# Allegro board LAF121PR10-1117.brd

Outline 228.4 x 155.5 mm; copper layers: TOP, GND1, IN1, VCC, IN2, IN3, GND2, BOTTOM. Coordinates in mm from the lower left corner of the outline.

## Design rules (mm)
net group APU-SINGLE CLK: nets 48M_X1 48M_X2
net group APU_DP3_AUX: nets APU_DP3_AUXN APU_DP3_AUXP
net group CSI_CHG: nets CSIN_CHG CSIP_CHG
net group CSO_CHG: nets CSON_CHG CSOP_CHG
net group DIFFPAIR15: nets NCT7718_DXN NCT7718_DXP
net group DIFFPAIR21: nets DDR_A_DQS0 DDR_A_DQS0#
net group DIFFPAIR22: nets DDR_A_DQS1 DDR_A_DQS1#
net group DIFFPAIR23: nets DDR_A_DQS2 DDR_A_DQS2#
net group DIFFPAIR24: nets DDR_A_DQS3 DDR_A_DQS3#
net group DIFFPAIR25: nets DDR_A_CLK0 DDR_A_CLK0#
net group DIFFPAIR26: nets DDR_A_CLK1 DDR_A_CLK1#
net group DIFFPAIR27: nets DDR_A_DQS4 DDR_A_DQS4#
net group DIFFPAIR28: nets DDR_A_DQS5 DDR_A_DQS5#
net group DIFFPAIR29: nets DDR_A_DQS6 DDR_A_DQS6#
net group DIFFPAIR30: nets DDR_A_DQS7 DDR_A_DQS7#
net group DIFFPAIR31: nets DDR_B_DQS0 DDR_B_DQS0#
net group DIFFPAIR32: nets DDR_B_DQS1 DDR_B_DQS1#
net group DIFFPAIR33: nets DDR_B_DQS2 DDR_B_DQS2#
net group DIFFPAIR34: nets DDR_B_DQS3 DDR_B_DQS3#
net group DIFFPAIR35: nets DDR_B_CLK1 DDR_B_CLK1#
net group DIFFPAIR36: nets DDR_B_CLK0 DDR_B_CLK0#
net group DIFFPAIR37: nets DDR_B_DQS4 DDR_B_DQS4#
net group DIFFPAIR38: nets DDR_B_DQS5 DDR_B_DQS5#
net group DIFFPAIR39: nets DDR_B_DQS6 DDR_B_DQS6#
net group DIFFPAIR40: nets DDR_B_DQS7 DDR_B_DQS7#
net group DIFFPAIR42: nets APU_SCLK0 APU_SDATA0
net group DIFFPAIR44: nets EC_SMB_CK2 EC_SMB_DA2
net group DIFFPAIR45: nets A_MIC_CLK A_MIC_DATA
net group DIFFPAIR46: nets EC_SMB_CK1 EC_SMB_DA1
net group DIFFPAIR47: nets TP_CLK TP_DATA
net group DIFFPAIR48: nets HDMI_CTRL_CLK HDMI_CTRL_DATA
net group DIFFPAIR49: nets AUD_HP1_JACK_L1 AUD_HP1_JACK_R1
net group DIFFPAIR54: nets N30684242 N30684245
net group GPU-XTAL_15/18_28/26: nets XTALIN XTALOUT
net group I2C: nets MIC_CLK_C MIC_DATA_C
net group VSUM_APU: nets VSUM+_APU VSUM-_APU
net group VSUM_VGA: nets VSUM+_VGA VSUM-_VGA
net group APU_CLK: nets CLK_PCIE_N1 CLK_PCIE_N2 CLK_PCIE_N3 CLK_PCIE_P1 CLK_PCIE_P2 CLK_PCIE_P3 CLK_PEG_N0 CLK_PEG_P0
net group AUDIO: nets LINE1-L_C LINE1-L_R RING2 RING2_R SLEEVE SLEEVE_R
net group CLK: nets SUSCLK_WLAN
net group CPU: nets H_PROCHOT#
net group DDR-MISCELLANEOUS: nets DDR_A_ALERT# DDR_A_EVENT# DDR_A_RST# DDR_B_ALERT# DDR_B_EVENT# DDR_B_RST#
net group DDR_A_ADD: nets DDR_A_BA0 DDR_A_BA1 DDR_A_BG0 DDR_A_BG1 DDR_A_MA0 DDR_A_MA1 DDR_A_MA2 DDR_A_MA3 DDR_A_MA4 DDR_A_MA5 DDR_A_MA6 DDR_A_MA7 DDR_A_MA8 DDR_A_MA9 DDR_A_MA10 DDR_A_MA11 DDR_A_MA12 DDR_A_MA13
net group DDR_A_CMD: nets DDR_A_ACT# DDR_A_MA14_WE# DDR_A_MA15_CAS# DDR_A_MA16_RAS#
net group DDR_A_CTL: nets DDR_A_CKE0 DDR_A_CKE1 DDR_A_CS0# DDR_A_CS1# DDR_A_ODT0 DDR_A_ODT1 DDR_A_PAR
net group DDR_B_ADD: nets DDR_B_BA0 DDR_B_BA1 DDR_B_BG0 DDR_B_BG1 DDR_B_MA0 DDR_B_MA1 DDR_B_MA2 DDR_B_MA3 DDR_B_MA4 DDR_B_MA5 DDR_B_MA6 DDR_B_MA7 DDR_B_MA8 DDR_B_MA9 DDR_B_MA10 DDR_B_MA11 DDR_B_MA12 DDR_B_MA13
net group DDR_B_CMD: nets DDR_B_ACT# DDR_B_MA14_WE# DDR_B_MA15_CAS# DDR_B_MA16_RAS#
net group DDR_B_CTL: nets DDR_B_CKE0 DDR_B_CKE1 DDR_B_CS0# DDR_B_CS1# DDR_B_ODT0 DDR_B_ODT1 DDR_B_PAR
net group DDRA_D0: nets DDR_A_DM0 DDR_A_DQ0 DDR_A_DQ1 DDR_A_DQ2 DDR_A_DQ3 DDR_A_DQ4 DDR_A_DQ5 DDR_A_DQ6 DDR_A_DQ7
net group DDRA_D1: nets DDR_A_DM1 DDR_A_DQ8 DDR_A_DQ9 DDR_A_DQ10 DDR_A_DQ11 DDR_A_DQ12 DDR_A_DQ13 DDR_A_DQ14 DDR_A_DQ15
net group DDRA_D2: nets DDR_A_DM2 DDR_A_DQ16 DDR_A_DQ17 DDR_A_DQ18 DDR_A_DQ19 DDR_A_DQ20 DDR_A_DQ21 DDR_A_DQ22 DDR_A_DQ23
net group DDRA_D3: nets DDR_A_DM3 DDR_A_DQ24 DDR_A_DQ25 DDR_A_DQ26 DDR_A_DQ27 DDR_A_DQ28 DDR_A_DQ29 DDR_A_DQ30 DDR_A_DQ31
net group DDRA_D4: nets DDR_A_DM4 DDR_A_DQ32 DDR_A_DQ33 DDR_A_DQ34 DDR_A_DQ35 DDR_A_DQ36 DDR_A_DQ37 DDR_A_DQ38 DDR_A_DQ39
net group DDRA_D5: nets DDR_A_DM5 DDR_A_DQ40 DDR_A_DQ41 DDR_A_DQ42 DDR_A_DQ43 DDR_A_DQ44 DDR_A_DQ45 DDR_A_DQ46 DDR_A_DQ47
net group DDRA_D6: nets DDR_A_DM6 DDR_A_DQ48 DDR_A_DQ49 DDR_A_DQ50 DDR_A_DQ51 DDR_A_DQ52 DDR_A_DQ53 DDR_A_DQ54 DDR_A_DQ55
net group DDRA_D7: nets DDR_A_DM7 DDR_A_DQ56 DDR_A_DQ57 DDR_A_DQ58 DDR_A_DQ59 DDR_A_DQ60 DDR_A_DQ61 DDR_A_DQ62 DDR_A_DQ63
net group DDRB_D0: nets DDR_B_DM0 DDR_B_DQ0 DDR_B_DQ1 DDR_B_DQ2 DDR_B_DQ3 DDR_B_DQ4 DDR_B_DQ5 DDR_B_DQ6 DDR_B_DQ7
net group DDRB_D1: nets DDR_B_DM1 DDR_B_DQ8 DDR_B_DQ9 DDR_B_DQ10 DDR_B_DQ11 DDR_B_DQ12 DDR_B_DQ13 DDR_B_DQ14 DDR_B_DQ15
net group DDRB_D2: nets DDR_B_DM2 DDR_B_DQ16 DDR_B_DQ17 DDR_B_DQ18 DDR_B_DQ19 DDR_B_DQ20 DDR_B_DQ21 DDR_B_DQ22 DDR_B_DQ23
net group DDRB_D3: nets DDR_B_DM3 DDR_B_DQ24 DDR_B_DQ25 DDR_B_DQ26 DDR_B_DQ27 DDR_B_DQ28 DDR_B_DQ29 DDR_B_DQ30 DDR_B_DQ31
net group DDRB_D4: nets DDR_B_DM4 DDR_B_DQ32 DDR_B_DQ33 DDR_B_DQ34 DDR_B_DQ35 DDR_B_DQ36 DDR_B_DQ37 DDR_B_DQ38 DDR_B_DQ39
net group DDRB_D5: nets DDR_B_DM5 DDR_B_DQ40 DDR_B_DQ41 DDR_B_DQ42 DDR_B_DQ43 DDR_B_DQ44 DDR_B_DQ45 DDR_B_DQ46 DDR_B_DQ47
net group DDRB_D6: nets DDR_B_DM6 DDR_B_DQ48 DDR_B_DQ49 DDR_B_DQ50 DDR_B_DQ51 DDR_B_DQ52 DDR_B_DQ53 DDR_B_DQ54 DDR_B_DQ55
net group DDRB_D7: nets DDR_B_DM7 DDR_B_DQ56 DDR_B_DQ57 DDR_B_DQ58 DDR_B_DQ59 DDR_B_DQ60 DDR_B_DQ61 DDR_B_DQ62 DDR_B_DQ63
net group DP: nets APU_DP2_AUXN APU_DP2_AUXN_C APU_DP2_AUXP APU_DP2_AUXP_C APU_DP2_N0 APU_DP2_N0_C APU_DP2_N1 APU_DP2_N1_C APU_DP2_P0 APU_DP2_P0_C APU_DP2_P1 APU_DP2_P1_C
net group EDP: nets EDP_AUXN EDP_AUXN_C EDP_AUXP EDP_AUXP_C EDP_TXN0 EDP_TXN0_C EDP_TXN1 EDP_TXN1_C EDP_TXP0 EDP_TXP0_C EDP_TXP1 EDP_TXP1_C
net group HDA: nets HDA_BIT_CLK HDA_BIT_CLK_R HDA_RST# HDA_SDIN0 HDA_SDIN0_R HDA_SDIN1 HDA_SDIN2 HDA_SDOUT HDA_SDOUT_R HDA_SYNC HDA_SYNC_R
net group HDMI: nets APU_DP1_CTRL_CLK APU_DP1_CTRL_DATA APU_DP1_N0 APU_DP1_N1 APU_DP1_N2 APU_DP1_N3 APU_DP1_P0 APU_DP1_P1 APU_DP1_P2 APU_DP1_P3 HDMI_CLKN HDMI_CLKP HDMI_L_CLKN HDMI_L_CLKP HDMI_L_TX_N0 HDMI_L_TX_N1 HDMI_L_TX_N2 HDMI_L_TX_P0 HDMI_L_TX_P1 HDMI_L_TX_P2 HDMI_TX_N0 HDMI_TX_N1 HDMI_TX_N2 HDMI_TX_P0 HDMI_TX_P1 HDMI_TX_P2
net group KB: nets KSI0 KSI1 KSI2 KSI3 KSI4 KSI5 KSI6 KSI7 KSO0 KSO1 KSO2 KSO3 KSO4 KSO5 KSO6 KSO7 KSO8 KSO9 KSO10 KSO11 KSO12 KSO13 KSO14 KSO15
net group LAN: nets LAN_MDIN0 LAN_MDIN1 LAN_MDIN2 LAN_MDIN3 LAN_MDIP0 LAN_MDIP1 LAN_MDIP2 LAN_MDIP3
net group LPC: nets CLKRUN# EC_SCI# LPC_AD0 LPC_AD1 LPC_AD2 LPC_AD3 LPC_CLK0_EC LPC_FRAME# LPC_RST_A# LPCI_CLK_TPM LPCPD# PLT_RST# SERIRQ
net group PCIE: nets PCIE_ARX_C_DTX_N4 PCIE_ARX_C_DTX_P4 PCIE_ARX_DTX_N0 PCIE_ARX_DTX_N1 PCIE_ARX_DTX_N2 PCIE_ARX_DTX_N3 PCIE_ARX_DTX_N4 PCIE_ARX_DTX_N5 PCIE_ARX_DTX_P0 PCIE_ARX_DTX_P1 PCIE_ARX_DTX_P2 PCIE_ARX_DTX_P3 PCIE_ARX_DTX_P4 PCIE_ARX_DTX_P5 PCIE_ATX_C_DRX_N0 PCIE_ATX_C_DRX_N1 PCIE_ATX_C_DRX_N2 PCIE_ATX_C_DRX_N3 PCIE_ATX_C_DRX_N4 PCIE_ATX_C_DRX_N5 PCIE_ATX_C_DRX_P0 PCIE_ATX_C_DRX_P1 PCIE_ATX_C_DRX_P2 PCIE_ATX_C_DRX_P3 PCIE_ATX_C_DRX_P4 PCIE_ATX_C_DRX_P5 PCIE_ATX_DRX_N0 PCIE_ATX_DRX_N1 PCIE_ATX_DRX_N2 PCIE_ATX_DRX_N3 PCIE_ATX_DRX_N4 PCIE_ATX_DRX_N5 PCIE_ATX_DRX_P0 PCIE_ATX_DRX_P1 PCIE_ATX_DRX_P2 PCIE_ATX_DRX_P3 PCIE_ATX_DRX_P4 PCIE_ATX_DRX_P5
net group PEG: nets PEG_ARX_C_GTX_N0 PEG_ARX_C_GTX_N1 PEG_ARX_C_GTX_N2 PEG_ARX_C_GTX_N3 PEG_ARX_C_GTX_P0 PEG_ARX_C_GTX_P1 PEG_ARX_C_GTX_P2 PEG_ARX_C_GTX_P3 PEG_ARX_GTX_N0 PEG_ARX_GTX_N1 PEG_ARX_GTX_N2 PEG_ARX_GTX_N3 PEG_ARX_GTX_P0 PEG_ARX_GTX_P1 PEG_ARX_GTX_P2 PEG_ARX_GTX_P3 PEG_ATX_C_GRX_N0 PEG_ATX_C_GRX_N1 PEG_ATX_C_GRX_N2 PEG_ATX_C_GRX_N3 PEG_ATX_C_GRX_P0 PEG_ATX_C_GRX_P1 PEG_ATX_C_GRX_P2 PEG_ATX_C_GRX_P3 PEG_ATX_GRX_N0 PEG_ATX_GRX_N1 PEG_ATX_GRX_N2 PEG_ATX_GRX_N3 PEG_ATX_GRX_P0 PEG_ATX_GRX_P1 PEG_ATX_GRX_P2 PEG_ATX_GRX_P3
net group RJ45: nets RJ45_MDIN0 RJ45_MDIN1 RJ45_MDIN2 RJ45_MDIN3 RJ45_MDIP0 RJ45_MDIP1 RJ45_MDIP2 RJ45_MDIP3
net group SATA: nets SATA_ARX_C_DTX_N0 SATA_ARX_C_DTX_N1 SATA_ARX_C_DTX_P0 SATA_ARX_C_DTX_P1 SATA_ARX_C_RD_DTX_N0 SATA_ARX_C_RD_DTX_P0 SATA_ARX_DTX_N0 SATA_ARX_DTX_N1 SATA_ARX_DTX_P0 SATA_ARX_DTX_P1 SATA_ARX_RD_DTX_N0 SATA_ARX_RD_DTX_P0 SATA_ATX_C_DRX_N0 SATA_ATX_C_DRX_N1 SATA_ATX_C_DRX_P0 SATA_ATX_C_DRX_P1 SATA_ATX_C_RD_DRX_N0 SATA_ATX_C_RD_DRX_P0 SATA_ATX_DRX_N0 SATA_ATX_DRX_N1 SATA_ATX_DRX_P0 SATA_ATX_DRX_P1 SATA_ATX_RD_DRX_N0 SATA_ATX_RD_DRX_P0 SATA_RX_N0 SATA_RX_P0 SATA_TX_N0 SATA_TX_P0
net group SMBUS: nets CLK_SMB DAT_SMB THM_SML1_CLK THM_SML1_DATA VGA_SMB_CK3 VGA_SMB_DA3
net group SPI: nets APU_SPI_CLK APU_SPI_CLK_R APU_SPI_CS1# APU_SPI_D0 APU_SPI_D1 APU_SPI_D2 APU_SPI_D3 APU_SPI_TPMCS#
net group SPK: nets INT-SPK-L+ INT-SPK-L- INT-SPK-R+ INT-SPK-R- SPK_L+_CONN SPK_L-_CONN SPK_R+_CONN SPK_R-_CONN
net group USB2.0: nets USB20_0_N0 USB20_0_N1 USB20_0_N1_R USB20_0_N2 USB20_0_N2_R USB20_0_N3 USB20_0_N3_R USB20_0_P0 USB20_0_P1 USB20_0_P1_R USB20_0_P2 USB20_0_P2_R USB20_0_P3 USB20_0_P3_R USB20_1_N0 USB20_1_N0_R USB20_1_N1 USB20_1_N1_R USB20_1_P0 USB20_1_P0_R USB20_1_P1 USB20_1_P1_R USB20_CR_N1 USB20_CR_N1_R USB20_CR_P1 USB20_CR_P1_R USB20_FP_N3 USB20_FP_P3 USB20_MINI1_N4 USB20_MINI1_P4 USB20_TOUCH_N2 USB20_TOUCH_P2
net group USB3.0: nets USB3_ARX_C_DTX_0_N1 USB3_ARX_C_DTX_0_N2 USB3_ARX_C_DTX_0_P1 USB3_ARX_C_DTX_0_P2 USB3_ARX_DTX_0_N1 USB3_ARX_DTX_0_N1_R USB3_ARX_DTX_0_N2 USB3_ARX_DTX_0_N2_R USB3_ARX_DTX_0_P1 USB3_ARX_DTX_0_P1_R USB3_ARX_DTX_0_P2 USB3_ARX_DTX_0_P2_R USB3_ATX_C_DRX_0_N1 USB3_ATX_C_DRX_0_N2 USB3_ATX_C_DRX_0_P1 USB3_ATX_C_DRX_0_P2 USB3_ATX_DRX_0_N1 USB3_ATX_DRX_0_N2 USB3_ATX_DRX_0_P1 USB3_ATX_DRX_0_P2 USB3_ATX_L_DRX_0_N1 USB3_ATX_L_DRX_0_N2 USB3_ATX_L_DRX_0_P1 USB3_ATX_L_DRX_0_P2 USB3_DP3_MRX_C_RD_DTX_N0 USB3_DP3_MRX_C_RD_DTX_N3 USB3_DP3_MRX_C_RD_DTX_P0 USB3_DP3_MRX_C_RD_DTX_P3 USB3_DP3_MRX_DTX_N0 USB3_DP3_MRX_DTX_N3 USB3_DP3_MRX_DTX_P0 USB3_DP3_MRX_DTX_P3 USB3_DP3_MRX_L_DTX_N0 USB3_DP3_MRX_L_DTX_N3 USB3_DP3_MRX_L_DTX_P0 USB3_DP3_MRX_L_DTX_P3 USB3_DP3_MRX_RD_DTX_N0 USB3_DP3_MRX_RD_DTX_N3 USB3_DP3_MRX_RD_DTX_P0 USB3_DP3_MRX_RD_DTX_P3 USB3_DP3_MTX_C_DRX_N1 USB3_DP3_MTX_C_DRX_N2 USB3_DP3_MTX_C_DRX_P1 USB3_DP3_MTX_C_DRX_P2 USB3_DP3_MTX_C_RD_DRX_N1 USB3_DP3_MTX_C_RD_DRX_N2 USB3_DP3_MTX_C_RD_DRX_P1 USB3_DP3_MTX_C_RD_DRX_P2 USB3_DP3_MTX_DRX_N1 USB3_DP3_MTX_DRX_N2 USB3_DP3_MTX_DRX_P1 USB3_DP3_MTX_DRX_P2 USB3_DP3_MTX_L_DRX_N1 USB3_DP3_MTX_L_DRX_N2 USB3_DP3_MTX_L_DRX_P1 USB3_DP3_MTX_L_DRX_P2 USB3_DP3_MTX_RD_DRX_N1 USB3_DP3_MTX_RD_DRX_N2 USB3_DP3_MTX_RD_DRX_P1 USB3_DP3_MTX_RD_DRX_P2
net group USB20: nets BOT_MUX_N BOT_MUX_N_R BOT_MUX_P BOT_MUX_P_R TOP_MUX_N TOP_MUX_N_R TOP_MUX_P TOP_MUX_P_R
net group VRAM-ADD0: nets M0_MA0 M0_MA1 M0_MA2 M0_MA3 M0_MA4 M0_MA5 M0_MA6 M0_MA7 M0_MA8
net group VRAM-ADD1: nets M1_MA0 M1_MA1 M1_MA2 M1_MA3 M1_MA4 M1_MA5 M1_MA6 M1_MA7 M1_MA8
net group VRAM-CLK: nets M_CLK0 M_CLK1 M_CLK#0 M_CLK#1
net group VRAM-CTL0: nets M_CAS#0 M_CKE0 M_CS0B#0 M_RAS#0 M_WE#0
net group VRAM-CTL1: nets M_CAS#1 M_CKE1 M_CS1B#0 M_RAS#1 M_WE#1
net group VRAM-D0: nets M_DA0 M_DA1 M_DA2 M_DA3 M_DA4 M_DA5 M_DA6 M_DA7
net group VRAM-D1: nets M_DA8 M_DA9 M_DA10 M_DA11 M_DA12 M_DA13 M_DA14 M_DA15
net group VRAM-D2: nets M_DA16 M_DA17 M_DA18 M_DA19 M_DA20 M_DA21 M_DA22 M_DA23
net group VRAM-D3: nets M_DA24 M_DA25 M_DA26 M_DA27 M_DA28 M_DA29 M_DA30 M_DA31
net group VRAM-D4: nets M_DA32 M_DA33 M_DA34 M_DA35 M_DA36 M_DA37 M_DA38 M_DA39
net group VRAM-D5: nets M_DA40 M_DA41 M_DA42 M_DA43 M_DA44 M_DA45 M_DA46 M_DA47
net group VRAM-D6: nets M_DA48 M_DA49 M_DA50 M_DA51 M_DA52 M_DA53 M_DA54 M_DA55
net group VRAM-D7: nets M_DA56 M_DA57 M_DA58 M_DA59 M_DA60 M_DA61 M_DA62 M_DA63
net group VRAM-DBI: nets M_ADBI0 M_ADBI1 M_DBI0# M_DBI1# M_DBI2# M_DBI3# M_DBI4# M_DBI5# M_DBI6# M_DBI7#
net group VRAM-EDC: nets M_EDC_0 M_EDC_1 M_EDC_2 M_EDC_3 M_EDC_4 M_EDC_5 M_EDC_6 M_EDC_7
net group VRAM-WCK: nets M_WCKA0_0 M_WCKA0_0# M_WCKA0_1 M_WCKA0_1# M_WCKA1_0 M_WCKA1_0# M_WCKA1_1 M_WCKA1_1#
nets with their own width: min track width 0.254; nets +3VLP +3VS_CAM +DP_VDDR +LAN_VDD33 +MPLL_PVDD +SPLL_PVDD +SPLL_VDDC +TSVDD +VDD_CT +VDDR3 KB_LED_PWM
nets with their own width: min track width 0.305; nets +3VS
nets with their own width: min track width 0.381; nets +1.8V_AVDD +3V_DVDD +5V_AVDD +17.4V_BATT+ +FB0_VREFCL +FB0_VREFDL +FB1_VREFCL +FB1_VREFDL +MVREFDA +MVREFSA
nets with their own width: min track width 0.508; nets +1.2VP +1.8VALWP +1.35V_MEM_GFX +2.5VP +3.3V_VDD_PIC +3VALW +5V_CONN_P1 +5VALW +5VS +DP_VDDC +VGA_CORE CCG4_CC1_P1 CCG4_CC2_P1 GND
nets with their own width: min track width 0.864; nets +5V_HDD
nets with their own width: min track width 1.016; nets +0.6V_DDR_VTT +2.5V_MEM MCT1
nets with their own width: min track width 1.219; nets +BIF_VDDC
nets with their own width: min track width 1.524; nets +0.6VSP +5V_HDMI +5VS_ODD +PCIE_VDDC
nets with their own width: min track width 2.032; nets +5V_PVDD +LCDVDD
nets with their own width: min track width 3.048; nets +CCG_VBUS
nets with their own width: min track width 3.81; nets +19VB

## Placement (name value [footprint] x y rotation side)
C1  10P_0402_50V8J  [C_0402]  148.56 56.64 0 top
C5  4.7U_0603_6.3V6K  [C_0603]  215.68 48.26 180 top
C12  0.1U_0603_25V7K  [C_0603]  203.42 59.37 90 top
C13  10U_0603_25V6M  [C_0603]  202.22 59.37 90 top
C14  4.7U_0603_6.3V6K  [C_0603]  214.28 45.78 0 top
C15  0.1U_0402_16V7K  [C_0402]  222.35 48.18 90 top
C16  1U_0402_10V6K  [C_0402]  221.46 48.18 90 top
C18  1U_0402_6.3V6K~D  [C_0402]  117 30.91 90 bottom
C19  10U_0603_10V6M  [C_0603]  95.28 36.25 0 top
C20  100P_0402_50V8J  [C_0402]  127.73 29.15 0 top
C21  100P_0402_50V8J  [C_0402]  127.73 28.27 0 top
C22  .1U_0402_16V7K  [C_0402]  106.21 29.35 270 top
C23  0.01U_0603_25V7K  [C_0603]  36.8 97.21 0 top
C24  1000P_0402_50V7K  [C_0402]  119.74 114.61 180 bottom
C25  0.1U_0402_10V6K  [C_0402]  119.74 115.57 180 bottom
C26  0.1U_0402_10V6K  [C_0402]  126.22 113.53 180 bottom
C27  1000P_0402_50V7K  [C_0402]  119.74 113.66 180 bottom
C28  470P_0402_50V7K  [C_0402]  43.91 98.05 270 top
C29  10U_0805_10V4Z  [C_0805]  49.88 102.64 270 top
C30  10U_0603_10V6M  [C_0603]  51.41 102.48 270 top
C31  0.1U_0402_10V6K  [C_0402]  126.22 112.58 180 bottom
C32  0.1U_0402_10V6K  [C_0402]  124.32 111.82 180 bottom
C33  0.1U_0402_10V6K  [C_0402]  121.62 111.82 0 bottom
C34  1U_0402_6.3V6K  [C_0402]  125.31 114.49 0 bottom
C35  0.01U_0603_25V7K  [C_0603]  33.24 50.67 0 top
C38  470P_0402_50V7K  [C_0402]  40.15 51.05 0 top
C39  10U_0603_6.3V6M  [C_0603]  41.12 55.75 0 top
C40  10U_0603_6.3V6M  [C_0603]  41.12 54.48 0 top
C41  330P_0402_50V7K  [C_0402]  41.07 49.72 180 top
C42  0.1U_0402_16V7K  [C_0402]  35.72 47.29 90 top
C43  1U_0402_6.3V6K  [C_0402]  36.67 47.29 90 top
C44  .1U_0402_16V7K  [C_0402]  37.56 47.29 90 top
C45  4.7U_0603_6.3V6K  [C_0603]  149.58 34.35 270 top
C46  4.7U_0603_6.3V6K  [C_0603]  153.96 39.17 0 top
C47  1U_0402_6.3V6K  [C_0402]  149.07 48.18 90 top
C48  10U_0603_6.3V6M  [C_0603]  31.91 51.37 270 top
C49  10U_0603_6.3V6M  [C_0603]  30.64 51.37 270 top
C50  10U_0603_10V6M  [C_0603]  38.54 100.08 90 top
C51  10U_0603_10V6M  [C_0603]  37.32 100.08 90 top
C52  .1U_0402_16V7K  [C_0402]  145.27 40.51 180 top
C53  10U_0603_6.3V6M  [C_0603]  180.76 62.23 0 top
C54  0.1U_0402_16V7K  [C_0402]  181 63.3 0 top
C55  470P_0603_50V8J  [C_0603]  111.79 110.93 0 bottom
C56  2200P_0402_50V7K  [C_0402]  182.26 61.25 225 bottom
C57  0.1U_0402_16V7K  [C_0402]  177.26 67.24 45 bottom
C58  0.1U_0402_16V7K  [C_0402]  176.63 66.61 225 bottom
C60  10U_0603_10V6M  [C_0603]  212.42 56.07 90 top
C61  0.01U_0402_16V7K  [C_0402]  212.57 53.86 270 top
C65  12P_0402_50V8J~N  [C_0402]  219.41 50.03 0 top
C66  12P_0402_50V8J~N  [C_0402]  216.9 50.03 180 top
C300  0.1U_0402_10V7K  [C_0402]  215.29 38.29 0 top
C301  0.1U_0402_10V7K  [C_0402]  215.29 37.4 0 top
C302  0.1U_0402_10V7K  [C_0402]  215.29 36.51 0 top
C303  0.1U_0402_10V7K  [C_0402]  215.29 35.62 0 top
C304  0.1U_0402_10V7K  [C_0402]  215.29 34.73 0 top
C305  0.1U_0402_10V7K  [C_0402]  215.29 33.84 0 top
C310  1U_0402_10V6K  [C_0402]  212.84 41.4 180 top
C636  10P_0402_50V8J  [C_0402]  120.7 36.32 180 bottom
C796  3.9P_0402_50V8B  [C_0402]  144.43 48.2 270 bottom
C797  3.9P_0402_50V8B  [C_0402]  144.43 49.07 90 bottom
C4311  0.1U_0402_16V7K  [C_0402]  210.8 52 180 bottom
C4312  0.1U_0402_16V7K  [C_0402]  210.8 51.11 180 bottom
C4313  0.1U_0402_16V7K  [C_0402]  210.8 50.22 180 bottom
C4314  0.1U_0402_16V7K  [C_0402]  210.8 49.33 180 bottom
C4321  0.1U_0402_16V7K  [C_0402]  210.8 53.78 180 bottom
C4322  0.1U_0402_16V7K  [C_0402]  210.8 52.89 180 bottom
CA1  10U_0603_10V6M  [C_0603]  31.78 7.68 270 top
CA2  .1U_0402_16V7K  [C_0402]  29.82 7.76 270 top
CA3  10U_0603_10V6M  [C_0603]  33.05 7.68 270 top
CA4  .1U_0402_16V7K  [C_0402]  30.7 7.76 270 top
CA6  10U_0603_10V6M  [C_0603]  21.18 17.27 180 top
CA7  .1U_0402_16V7K  [C_0402]  39.34 20.87 90 top
CA9  10U_0603_10V6M  [C_0603]  32.06 9.29 0 top
CA10  .1U_0402_16V7K  [C_0402]  20.94 18.35 180 top
CA12  10U_0603_10V6M  [C_0603]  21.12 8.25 270 top
CA14  .1U_0402_16V7K  [C_0402]  37.7 20.89 180 top
CA16  10U_0603_10V6M  [C_0603]  36.31 9.08 0 top
CA17  .1U_0402_16V7K  [C_0402]  32.41 15.17 0 top
CA19  10U_0603_10V6M  [C_0603]  19.97 15.24 0 top
CA20  10U_0603_6.3V6M  [C_0603]  23.78 6.15 90 top
CA21  10U_0603_10V6M  [C_0603]  37.56 13.52 180 top
CA23  2.2U_0603_6.3V6K  [C_0603]  21.37 13.97 180 top
CA24  1U_0603_16V7  [C_0603]  22.08 9.7 315 top
CA25  .1U_0402_16V7K  [C_0402]  26.01 22.04 270 top
CA26  .1U_0402_16V7K  [C_0402]  8.92 20.46 270 top
CA27  .1U_0402_16V7K  [C_0402]  22.2 6.97 90 top
CA28  .1U_0402_16V7K  [C_0402]  24.42 21.85 270 top
CA29  .1U_0402_16V7K  [C_0402]  31.1 20.32 180 top
CA30  1000P_0402_50V7K  [C_0402]  22.2 5.19 90 top
CA31  22P_0402_50V8J  [C_0402]  34.32 14.02 90 top
CA37  10U_0603_10V6M  [C_0603]  22.32 18.22 90 top
CA38  10U_0603_10V6M  [C_0603]  23.53 18.22 90 top
CA39  100P_0402_50V8J  [C_0402]  17.29 18.35 0 bottom
CA40  100P_0402_50V8J  [C_0402]  16.43 18.35 180 bottom
CA41  680P_0402_50V8J  [C_0402]  18.21 13.39 180 bottom
CA42  680P_0402_50V8J  [C_0402]  15.45 13.39 0 bottom
CA46  .1U_0402_16V7K  [C_0402]  32.06 10.4 0 top
CA47  0.1U_0402_16V7K  [C_0402]  33.38 16.95 180 top
CA48  .1U_0402_16V7K  [C_0402]  30.64 18.52 90 top
CA49  10P_0402_50V8J  [C_0402]  36.41 12.38 0 top
CA50  10P_0402_50V8J  [C_0402]  36.41 11.49 0 top
CA51  10P_0402_50V8J  [C_0402]  36.41 10.54 0 top
CA52  1000P_0402_50V7K  [C_0402]  27.9 6.28 0 top
CA53  10U_0603_10V6M  [C_0603]  24.99 7.55 270 top
CA54  1U_0603_16V7  [C_0603]  19.91 6.85 90 top
CA55  1000P_0402_50V7K  [C_0402]  26.97 6.28 180 top
CA56  10U_0603_6.3V6M  [C_0603]  26.7 18.73 180 top
CA57  0.1U_0402_16V7K  [C_0402]  27.72 19.41 90 top
CA66  1000P_0402_50V7K  [C_0402]  22.2 3.82 270 top
CA67  680P_0402_50V8J  [C_0402]  15.45 14.35 0 bottom
CA68  680P_0402_50V8J  [C_0402]  18.21 14.35 180 bottom
CC1  .1U_0402_16V7K  [C_0402]  28.69 83.18 180 top
CC2  .1U_0402_16V7K  [C_0402]  28.69 84.07 180 top
CC3  .1U_0402_16V7K  [C_0402]  77.76 116.76 90 bottom
CC4  .1U_0402_16V7K  [C_0402]  76.87 116.76 90 bottom
CC5  27P_0402_50V8F  [C_0402]  145.14 57.34 180 bottom
CC6  27P_0402_50V8F  [C_0402]  148.55 59.24 0 top
CC7  150P_0402_50V8J  [C_0402]  106.78 118.92 90 bottom
CC8  100P_0402_50V8J  [C_0402]  42.67 62.75 0 top
CC9  .1U_0402_16V7K  [C_0402]  43.58 63.7 180 top
CC10  .1U_0402_16V7K  [C_0402]  43.93 61.79 180 top
CC11  0.1U_0402_16V7K  [C_0402]  123.1 57.48 270 top
CC12  0.1U_0402_16V7K  [C_0402]  119.74 50.35 180 top
CC13  0.1U_0402_16V7K  [C_0402]  132.88 46.43 270 top
CC14  0.1U_0402_16V7K  [C_0402]  144.36 57.27 0 top
CC15  1U_0603_25V6K  [C_0603]  119.92 52.19 180 top
CC16  10U_0603_6.3V6M  [C_0603]  119.92 53.46 180 top
CC21  22U_0603_6.3V6M  [C_0603]  94.78 62.92 270 top
CC22  22U_0603_6.3V6M  [C_0603]  92.11 84.32 90 top
CC23  22U_0603_6.3V6M  [C_0603]  116.81 75.05 90 top
CC24  22U_0603_6.3V6M  [C_0603]  61.44 66.73 270 top
CC25  22U_0603_6.3V6M  [C_0603]  83.35 84.39 90 top
CC26  22U_0603_6.3V6M  [C_0603]  96.05 62.92 270 top
CC27  22U_0603_6.3V6M  [C_0603]  90.84 84.32 90 top
CC28  22U_0603_6.3V6M  [C_0603]  93.38 84.32 90 top
CC29  22U_0603_6.3V6M  [C_0603]  97.32 62.92 270 top
CC30  1U_0402_6.3V6K  [C_0402]  101.25 62.62 270 top
CC31  1U_0402_6.3V6K  [C_0402]  100.3 62.62 270 top
CC32  180P_0402_50V8J  [C_0402]  119.29 76.12 90 top
CC33  180P_0402_50V8J  [C_0402]  98.4 62.62 270 top
CC34  180P_0402_50V8J  [C_0402]  99.35 62.62 270 top
CC35  0.22U_0402_10V6K  [C_0402]  117.9 61.08 180 top
CC36  0.22U_0402_10V6K  [C_0402]  116.87 72.18 90 top
CC37  0.22U_0402_10V6K  [C_0402]  94.46 84.56 90 top
CC38  0.22U_0402_10V6K  [C_0402]  95.41 84.56 90 top
CC39  180P_0402_50V8J  [C_0402]  129.07 64.31 90 top
CC40  22U_0603_6.3V6M  [C_0603]  128.76 73.6 90 top
CC41  22U_0603_6.3V6M  [C_0603]  123.99 71.8 270 top
CC42  22U_0603_6.3V6M  [C_0603]  128.71 76.81 90 top
CC43  22U_0603_6.3V6M  [C_0603]  126.42 71.8 270 top
CC44  22U_0603_6.3V6M  [C_0603]  126.32 73.6 90 top
CC45  22U_0603_6.3V6M  [C_0603]  128.86 71.8 270 top
CC46  22U_0603_6.3V6M  [C_0603]  127.54 73.6 90 top
CC47  22U_0603_6.3V6M  [C_0603]  122.77 71.8 270 top
CC48  22U_0603_6.3V6M  [C_0603]  125.1 73.6 90 top
CC49  22U_0603_6.3V6M  [C_0603]  126.27 76.83 90 top
CC50  22U_0603_6.3V6M  [C_0603]  123.88 67.22 90 top
CC51  22U_0603_6.3V6M  [C_0603]  127.49 76.81 90 top
CC52  22U_0603_6.3V6M  [C_0603]  122.67 67.2 90 top
CC53  22U_0603_6.3V6M  [C_0603]  127.64 71.8 270 top
CC54  22U_0603_6.3V6M  [C_0603]  125.21 71.8 270 top
CC55  22U_0603_6.3V6M  [C_0603]  125.09 67.22 90 top
CC56  22U_0603_6.3V6M  [C_0603]  125.05 76.81 90 top
CC57  22U_0603_6.3V6M  [C_0603]  123.83 76.81 90 top
CC58  22U_0603_6.3V6M  [C_0603]  122.61 76.81 90 top
CC59  22U_0603_6.3V6M  [C_0603]  122.67 73.6 90 top
CC60  22U_0603_6.3V6M  [C_0603]  123.88 73.6 90 top
CC61  180P_0402_50V8J  [C_0402]  126.01 79.26 90 top
CC62  1U_0402_6.3V6K  [C_0402]  121.55 79.03 270 top
CC63  22U_0603_6.3V6M  [C_0603]  122.78 79.5 90 top
CC64  22U_0603_6.3V6M  [C_0603]  121.22 73.86 270 top
CC65  10U_0603_6.3V6M  [C_0603]  124.96 62.35 270 top
CC66  22U_0603_6.3V6M  [C_0603]  123.8 43.3 90 top
CC67  1U_0402_6.3V6K  [C_0402]  122.47 43.87 180 bottom
CC68  1U_0402_6.3V6K  [C_0402]  122.47 44.76 180 bottom
CC69  22U_0603_6.3V6M  [C_0603]  117 47.43 90 top
CC70  1U_0402_6.3V6K  [C_0402]  119.03 47.67 90 top
CC71  1U_0402_6.3V6K  [C_0402]  118.08 47.67 90 top
CC72  22U_0603_6.3V6M  [C_0603]  121.76 61.72 90 top
CC73  1U_0402_6.3V6K  [C_0402]  131.78 86.99 0 top
CC74  1U_0402_6.3V6K  [C_0402]  123.08 45.65 0 top
CC75  22U_0603_6.3V6M  [C_0603]  150.78 34.35 270 top
CC76  1U_0402_6.3V6K  [C_0402]  148.5 34.17 270 top
CC77  1U_0402_6.3V6K  [C_0402]  152.82 34.11 270 top
CC78  1U_0402_6.3V6K  [C_0402]  151.86 34.11 270 top
CC79  22U_0603_6.3V6M  [C_0603]  153.96 40.38 0 top
CC80  22U_0603_6.3V6M  [C_0603]  153.96 41.59 0 top
CC81  1U_0402_6.3V6K  [C_0402]  153.44 46.16 0 top
CC82  1U_0402_6.3V6K  [C_0402]  131.5 57.81 270 top
CC83  1U_0402_6.3V6K  [C_0402]  150.91 48.18 90 top
CC84  1U_0402_6.3V6K  [C_0402]  153.44 44.32 0 top
CC85  1U_0402_6.3V6K  [C_0402]  153.44 43.43 0 top
CC86  1U_0402_6.3V6K  [C_0402]  153.44 45.21 0 top
CC87  1U_0402_6.3V6K  [C_0402]  153.44 47.11 0 top
CC88  1U_0402_6.3V6K  [C_0402]  129.02 62.34 90 top
CC89  180P_0402_50V8J  [C_0402]  149.96 48.18 90 top
CC90  0.22U_0402_10V6K  [C_0402]  133.13 34.27 90 bottom
CC91  1U_0402_6.3V6K  [C_0402]  134.08 34.27 90 bottom
CC92  0.1U_0603_25V7K  [C_0603]  151.55 27.94 90 top
CC93  680P_0603_50V8J  [C_0603]  154.85 31.3 180 top
CC94  0.1U_0402_16V7K  [C_0402]  142.97 43.76 270 bottom
CC95  0.1U_0402_16V7K  [C_0402]  142.97 44.62 90 bottom
CC100  150P_0402_50V8J  [C_0402]  111.03 117.55 270 bottom
CC250  0.1U_0402_16V7K  [C_0402]  145.14 58.22 180 bottom
CC251  0.1U_0402_16V7K  [C_0402]  226.3 57.15 180 top
CC615  150P_0402_50V8J  [C_0402]  128.49 43.23 90 top
CC635  .1U_0402_16V7K  [C_0402]  121.62 43.43 0 top
CC682  15P_0402_50V8J  [C_0402]  144.37 53.03 270 bottom
CC686  18P_0402_50V8J  [C_0402]  144.37 53.89 90 bottom
CC1189  1U_0402_6.3V6K  [C_0402]  122.28 51.62 180 top
CC1190  1U_0402_6.3V6K  [C_0402]  122.28 52.57 180 top
CC1191  22U_0603_6.3V6M  [C_0603]  143.54 65.15 0 bottom
CC1192  1U_0402_6.3V6K  [C_0402]  143.85 64.07 0 bottom
CC1193  0.1U_0603_25V7K  [C_0603]  130.53 26.98 270 bottom
CD1  100P_0402_50V8J  [C_0402]  71.54 83.23 90 top
CD2  10U_0603_6.3V6M  [C_0603]  63.41 83.05 90 top
CD3  10U_0603_6.3V6M  [C_0603]  65.95 83.05 90 top
CD4  10U_0603_6.3V6M  [C_0603]  62.65 66.73 270 top
CD5  10U_0603_6.3V6M  [C_0603]  82.08 84.39 90 top
CD6  10U_0603_6.3V6M  [C_0603]  62.14 83.05 90 top
CD7  10U_0603_6.3V6M  [C_0603]  60.87 83.05 90 top
CD8  1U_0402_6.3V6K  [C_0402]  82.58 62.49 270 top
CD9  1U_0402_6.3V6K  [C_0402]  70.65 82.91 90 top
CD10  1U_0402_6.3V6K  [C_0402]  45.68 32 0 top
CD11  1U_0402_6.3V6K  [C_0402]  65.95 66.49 270 top
CD12  1U_0402_6.3V6K  [C_0402]  78.39 84.76 90 top
CD13  1U_0402_6.3V6K  [C_0402]  87.35 62.49 270 top
CD14  1U_0402_6.3V6K  [C_0402]  85.44 62.49 270 top
CD15  1U_0402_6.3V6K  [C_0402]  76.49 84.76 90 top
CD16  1U_0402_6.3V6K  [C_0402]  58.85 43.8 90 top
CD17  10U_0603_6.3V6M  [C_0603]  69.25 42.41 90 top
CD18  10U_0603_6.3V6M  [C_0603]  70.52 42.41 90 top
CD19  10P_0402_50V8J  [C_0402]  83.54 62.49 270 top
CD20  10P_0402_50V8J  [C_0402]  66.9 66.49 270 top
CD21  10P_0402_50V8J  [C_0402]  73.63 84.76 90 top
CD22  10P_0402_50V8J  [C_0402]  57.95 43.8 90 top
CD23  10P_0402_50V8J  [C_0402]  76.04 43.45 90 top
CD24  4.7U_0402_6.3V6K  [C_0402]  71.67 65.53 180 top
CD25  0.1U_0402_16V4Z  [C_0402]  73.05 66.42 0 top
CD26  0.1U_0402_16V4Z  [C_0402]  71.67 66.42 180 top
CD27  2.2U_0402_6.3V6M  [C_0402]  64.99 66.49 270 top
CD28  2.2U_0402_6.3V6M  [C_0402]  84.49 62.49 270 top
CD29  2.2U_0402_6.3V6M  [C_0402]  79.35 84.76 90 top
CD30  2.2U_0402_6.3V6M  [C_0402]  75.09 43.45 90 top
CD31  2.2U_0402_6.3V6M  [C_0402]  74.2 43.45 90 top
CD32  1000P_0402_50V7K  [C_0402]  73.05 65.53 0 top
CD34  10U_0603_6.3V6M  [C_0603]  57.57 49.33 0 top
CD35  330U_D2_2V_Y  [C_D2]  87.73 81 90 top
CD36  1U_0402_6.3V6K  [C_0402]  64.8 42.72 90 top
CD37  10U_0603_6.3V6M  [C_0603]  67.09 42.48 90 top
CD38  1U_0402_6.3V6K  [C_0402]  75.27 45.84 0 top
CD39  1U_0402_6.3V6K  [C_0402]  79.6 43.33 90 top
CD40  100P_0402_50V8J  [C_0402]  59.53 83.93 90 top
CD41  10U_0603_6.3V6M  [C_0603]  63.92 66.73 270 top
CD42  10U_0603_6.3V6M  [C_0603]  84.62 84.39 90 top
CD43  10U_0603_6.3V6M  [C_0603]  64.68 83.05 90 top
CD44  10U_0603_6.3V6M  [C_0603]  78.33 65.53 270 top
CD45  10U_0603_6.3V6M  [C_0603]  67.22 83.05 90 top
CD46  10U_0603_6.3V6M  [C_0603]  69.57 82.99 90 top
CD47  1U_0402_6.3V6K  [C_0402]  77.44 84.76 90 top
CD48  1U_0402_6.3V6K  [C_0402]  74.58 84.76 90 top
CD49  1U_0402_6.3V6K  [C_0402]  86.39 62.49 270 top
CD50  1U_0402_6.3V6K  [C_0402]  96.36 84.56 90 top
CD51  1U_0402_6.3V6K  [C_0402]  80.3 84.76 90 top
CD52  1U_0402_6.3V6K  [C_0402]  68.49 82.91 90 top
CD53  1U_0402_6.3V6K  [C_0402]  81.63 62.49 270 top
CD54  1U_0402_6.3V6K  [C_0402]  75.54 84.76 90 top
CD55  1U_0402_6.3V6K  [C_0402]  68.17 42.65 90 top
CD56  10U_0603_6.3V6M  [C_0603]  71.79 42.41 90 top
CD57  10U_0603_6.3V6M  [C_0603]  73.06 42.41 90 top
CD58  1000P_0402_50V7K  [C_0402]  58.97 66.42 180 top
CD59  4.7U_0402_6.3V6K  [C_0402]  58.64 65.48 270 top
CD60  0.1U_0402_16V4Z  [C_0402]  59.53 65.48 270 top
CD61  0.1U_0402_16V4Z  [C_0402]  58.97 68.07 180 top
CD64  1U_0402_6.3V6K  [C_0402]  78.65 43.33 90 top
CD65  10U_0603_6.3V6M  [C_0603]  57.57 50.54 0 top
CD66  10U_0603_6.3V6M  [C_0603]  65.88 42.48 90 top
CD67  1U_0402_6.3V6K  [C_0402]  65.88 44.88 90 top
CD68  1U_0402_6.3V6K  [C_0402]  77.69 43.33 90 top
CE1  1U_0603_10V6K  [C_0603]  91.03 35.94 90 top
CE2  0.1U_0402_16V7K  [C_0402]  44.93 65.54 270 top
CE3  1000P_0402_50V7K  [C_0402]  54.21 69.85 180 top
CE4  0.1U_0402_16V7K  [C_0402]  40.29 65.54 270 top
CE5  0.1U_0402_16V7K  [C_0402]  31.86 70.35 180 top
CE6  0.1U_0402_16V7K  [C_0402]  37.36 85.28 0 top
CE7  1000P_0402_50V7K  [C_0402]  38.27 86.23 180 top
CE8  0.1U_0402_16V7K  [C_0402]  47.85 86.2 270 top
CE9  0.1U_0402_16V7K  [C_0402]  50.39 85.29 90 top
CE11  100P_0402_50V8J  [C_0402]  53.4 82.76 270 top
CE12  22P_0402_50V8J  [C_0402]  41.18 63.83 270 top
CE13  0.1U_0402_16V7K  [C_0402]  53.3 70.8 0 top
CE14  100P_0402_50V8J  [C_0402]  32.72 77.15 0 top
CE16  1000P_0402_50V7K  [C_0402]  33.64 80.77 180 top
CE17  0.1U_0402_16V7K  [C_0402]  31.86 71.31 180 top
CE18  0.1U_0402_16V7K  [C_0402]  38.52 64.63 90 top
CE19  0.1U_0402_16V7K  [C_0402]  31.53 64.18 90 top
CF1  22U_0805_10V6M  [C_0805]  178.88 69.34 180 top
CH2  0.01U_0402_16V7K  [C_0402]  226.3 58.22 180 top
CH3  0.01U_0402_16V7K  [C_0402]  222.93 67.5 180 top
CH4  0.01U_0402_16V7K  [C_0402]  221.4 64.74 90 top
CI1  0.1U_0402_10V7K  [C_0402]  18.56 94.36 0 top
CI2  0.1U_0402_10V7K  [C_0402]  18.56 93.47 0 top
CI3  .1U_0402_16V7K  [C_0402]  15.9 99.88 0 top
CI4  0.1U_0402_10V7K  [C_0402]  20.91 96.2 0 top
CI5  0.1U_0402_10V7K  [C_0402]  20.91 95.31 0 top
CI6  0.1U_0402_10V7K  [C_0402]  20.91 92.45 0 top
CI7  0.1U_0402_10V7K  [C_0402]  20.91 91.56 0 top
CI8  0.1U_0402_10V7K  [C_0402]  18.56 90.42 0 top
CI9  0.1U_0402_10V7K  [C_0402]  18.56 89.53 0 top
CI10  220P_0402_50V8J  [C_0402]  17.69 106.47 90 top
CL3  1U_0402_6.3V6K  [C_0402]  23.67 88.83 180 top
CL4  .1U_0402_16V7K  [C_0402]  20.3 79.56 180 bottom
CL5  .1U_0402_16V7K  [C_0402]  25.43 82.69 270 bottom
CL6  .1U_0402_16V7K  [C_0402]  23.01 86.48 0 bottom
CL7  0.1U_0402_10V7K  [C_0402]  28.69 85.97 180 top
CL8  0.1U_0402_10V7K  [C_0402]  28.69 86.86 180 top
CL9  0.01U_0402_16V7K  [C_0402]  27.47 69.64 90 top
CL10  10P_1206_2KV8J  [C_1206]  21.5 76.64 0 bottom
CL11  10P_0402_50V8J  [C_0402]  17.75 84.83 90 top
CL12  10P_0402_50V8J  [C_0402]  17.75 83.84 270 top
CL15  .1U_0402_16V7K  [C_0402]  21.62 84.46 270 bottom
CL18  .1U_0402_16V7K  [C_0402]  18.89 81.4 180 top
CL19  .1U_0402_16V7K  [C_0402]  18.73 80.58 180 bottom
CL20  .1U_0402_16V7K  [C_0402]  22.21 79.88 180 bottom
CL21  .1U_0402_16V7K  [C_0402]  24.81 79.94 180 bottom
CL22  1U_0402_10V6K  [C_0402]  22.94 84.74 0 bottom
CL23  .1U_0402_16V7K  [C_0402]  24.74 85.64 270 bottom
CL24  4.7U_0603_6.3V6K  [C_0603]  25.43 83.71 0 bottom
CL25  4.7U_0603_6.3V6K  [C_0603]  21.5 80.83 90 bottom
CLIP2  -  [EMIST_SQ-55G_1P]  84.74 119.23 180 bottom
CLRP1  SHORT PADS  [SHORTPADS]  131.99 34.98 90 bottom
CS1  0.01U_0402_16V7K  [C_0402]  178.75 37 270 top
CS2  0.1U_0402_25V6K  [C_0402]  179.68 37 270 top
CS3  0.01U_0402_16V7K  [C_0402]  179.6 34.98 0 top
CS4  0.01U_0402_16V7K  [C_0402]  179.6 34.09 0 top
CS5  0.01U_0402_16V7K  [C_0402]  179.6 32.32 0 top
CS6  0.01U_0402_16V7K  [C_0402]  179.6 33.21 0 top
CS7  0.01U_0402_16V7K  [C_0402]  188.17 34.16 0 top
CS8  0.01U_0402_16V7K  [C_0402]  188.17 33.27 0 top
CS9  0.01U_0402_16V7K  [C_0402]  188.17 31.43 0 top
CS10  0.01U_0402_16V7K  [C_0402]  188.17 32.32 0 top
CS11  0.01U_0402_16V7K  [C_0402]  191.31 34.16 180 top
CS12  10U_0805_10V6K  [C_0805]  195.3 39.59 90 top
CS13  1000P_0402_50V7K  [C_0402]  193.07 39.99 90 top
CS14  0.1U_0402_25V6K  [C_0402]  193.96 39.99 90 top
CS15  0.01U_0402_16V7K  [C_0402]  191.31 33.27 180 top
CS16  0.01U_0402_16V7K  [C_0402]  191.31 31.43 180 top
CS17  0.01U_0402_16V7K  [C_0402]  191.31 32.32 180 top
CS18  0.01U_0402_16V7K  [C_0402]  188.06 63.74 90 top
CS19  0.01U_0402_16V7K  [C_0402]  188.95 63.74 90 top
CS20  0.1U_0402_25V6K  [C_0402]  203.23 32.9 270 top
CS21  10U_0805_10V6K  [C_0805]  207.4 31.36 0 top
CS22  0.01U_0402_16V7K  [C_0402]  190.72 63.74 90 top
CS23  0.01U_0402_16V7K  [C_0402]  189.84 63.74 90 top
CS24  1000P_0402_50V7K  [C_0402]  196.12 62.87 270 top
CS25  0.1U_0402_25V6K  [C_0402]  195.17 62.87 270 top
CS26  10U_0805_10V6K  [C_0805]  194.12 62.42 180 top
CS29  0.1U_0402_25V6K~D  [C_0402]  28.22 30.54 0 top
CS31  10U_0805_25V6K~D  [C_0805]  22.08 31.59 90 top
CS32  1U_0402_6.3V6K~D  [C_0402]  28.22 29.59 0 top
CS33  1000P_0402_50V7K~D  [C_0402]  28.22 31.43 0 top
CS40  1U_0402_10V6K  [C_0402]  192.82 37.03 270 top
CS44  0.22U_0402_16V7K  [C_0402]  27.34 37.03 270 bottom
CS45  0.22U_0402_16V7K  [C_0402]  31.21 37.03 270 bottom
CS46  0.22U_0402_16V7K  [C_0402]  28.29 37.03 270 bottom
CS47  0.22U_0402_16V7K  [C_0402]  30.26 37.03 270 bottom
CS48  0.22U_0402_16V7K  [C_0402]  34.26 37.03 270 bottom
CS49  0.22U_0402_16V7K  [C_0402]  33.31 37.03 270 bottom
CS50  0.22U_0402_16V7K  [C_0402]  36.17 36.97 270 bottom
CS51  0.22U_0402_16V7K  [C_0402]  37.12 36.97 270 bottom
CS70  22U_0603_6.3V6M  [C_0603]  27.72 33.27 0 top
CS71  22U_0603_6.3V6M  [C_0603]  27.72 34.48 0 top
CS72  47U_0805_6.3V6M  [C_0805]  25.5 31.59 90 top
CS73  47U_0805_6.3V6M  [C_0805]  23.78 31.59 90 top
CT3  1U_0603_16V7  [C_0603]  36.23 111.18 270 top
CT4  0.1U_0402_10V7K  [C_0402]  41.26 122.08 0 top
CT5  1U_0603_16V7  [C_0603]  35.21 126.04 270 top
CT6  0.1U_0402_10V7K  [C_0402]  34.51 128.19 90 bottom
CT7  0.1U_0402_10V7K  [C_0402]  33.56 128.19 90 bottom
CT8  1U_0603_16V7  [C_0603]  36.42 126.04 270 top
CT9  0.1U_0402_10V7K  [C_0402]  35.92 120.52 180 top
CT10  390P_0402_50V7K  [C_0402]  41.04 122.99 0 top
CT11  390P_0402_50V7K  [C_0402]  39.35 122.04 180 top
CT12  0.1U_0402_10V7K  [C_0402]  32.04 111.68 90 top
CT13  0.1U_0402_10V7K  [C_0402]  40.79 112.96 0 top
CT17  2.2U_0603_10V6K  [C_0603]  26.6 118.74 90 top
CT21  10U_0603_25V6M  [C_0603]  18.45 130.61 90 top
CT22  22U_0805_25V6M  [C_0805]  16.86 130.4 90 top
CT26  0.47U_0402_50V6K  [C_0402]  11.34 117.36 270 bottom
CT27  0.47U_0402_50V6K  [C_0402]  11.4 123.62 90 bottom
CT28  0.47U_0402_50V6K  [C_0402]  10.45 123.62 90 bottom
CT29  0.47U_0402_50V6K  [C_0402]  10.38 117.36 270 bottom
CT32  0.1U_0402_10V7K  [C_0402]  17.84 116.81 180 top
CT33  0.1U_0402_10V7K  [C_0402]  21.5 116.76 90 top
CT34  0.1U_0402_10V7K  [C_0402]  22.45 116.76 90 top
CT35  0.1U_0402_10V7K  [C_0402]  20.54 116.76 90 top
CT36  0.1U_0402_10V7K  [C_0402]  19.59 116.76 90 top
CT37  0.1U_0402_10V7K  [C_0402]  25.19 125.6 180 bottom
CT38  0.1U_0402_10V7K  [C_0402]  25.19 124.71 180 bottom
CT39  0.1U_0402_10V7K  [C_0402]  25.19 119.38 180 bottom
CT40  0.1U_0402_10V7K  [C_0402]  25.19 120.26 180 bottom
CT41  0.1U_0402_10V7K  [C_0402]  25.19 123.82 180 bottom
CT42  0.1U_0402_10V7K  [C_0402]  25.19 122.93 180 bottom
CT43  0.1U_0402_10V7K  [C_0402]  25.19 121.15 180 bottom
CT44  0.1U_0402_10V7K  [C_0402]  25.19 122.04 180 bottom
CT45  0.1U_0402_10V7K  [C_0402]  19.52 116.7 90 bottom
CT46  0.1U_0402_10V7K  [C_0402]  20.61 127.36 90 top
CT47  0.1U_0402_10V7K  [C_0402]  18.63 116.7 90 bottom
CT49  22U_0805_10V6M  [C_0805]  43 114.55 0 top
CT50  4.7U_0603_6.3V6K  [C_0603]  43.15 113.03 0 top
CT53  1U_0603_25V6  [C_0603]  32.36 119.31 0 top
CT54  1U_0402_16V6K  [C_0402]  34.96 117.27 90 top
CT55  0.1U_0402_25V6  [C_0402]  28.79 112.96 0 top
CT56  1U_0603_25V  [C_0603]  28.48 114.04 0 top
CT57  22U_0805_25V6M  [C_0805]  13.12 117.11 270 bottom
CT58  0.1U_0402_10V7K  [C_0402]  14.33 123.88 180 top
CT59  0.1U_0402_10V7K  [C_0402]  14.33 122.99 180 top
CT60  0.1U_0402_10V7K  [C_0402]  15.6 118.11 180 top
CT61  0.1U_0402_10V7K  [C_0402]  15.6 117.22 180 top
CT62  10U 6.3V  0402  [C_0402]  32.27 131.26 270 top
CU1  47U_0805_6.3V4Z  [C_0805]  21.62 59.22 90 bottom
CU2  47U_0805_6.3V4Z  [C_0805]  18.93 54.48 0 top
CU3  10U_0603_10V6M  [C_0603]  20.1 59.43 90 bottom
CU4  0.1U_0402_16V7K  [C_0402]  19.39 55.88 0 top
CU5  4.7U_0805_10V4Z  [C_0805]  18.58 51.52 270 bottom
CU6  0.1U_0402_16V7K  [C_0402]  19.03 52.57 180 bottom
CU7  0.22U_0402_10V6K  [C_0402]  23.71 59.18 0 top
CU8  0.22U_0402_10V6K  [C_0402]  23.71 60.13 0 top
CU9  0.1U_0402_16V7K  [C_0402]  20.86 52.71 270 bottom
CU10  0.1U_0402_16V7K  [C_0402]  20.81 57.27 180 bottom
CU11  47U_0805_6.3V4Z  [C_0805]  18.93 50.67 0 top
CU12  47U_0805_6.3V4Z  [C_0805]  18.93 48.89 0 top
CU13  10U_0603_10V6M  [C_0603]  19.08 47.37 0 top
CU14  0.1U_0402_16V7K  [C_0402]  15.79 41.91 180 top
CU15  0.22U_0402_10V6K  [C_0402]  19.4 38.59 90 top
CU16  0.22U_0402_10V6K  [C_0402]  18.39 38.59 90 top
CU17  4.7U_0805_10V4Z  [C_0805]  202.35 35.94 45 top
CU18  0.1U_0402_16V7K  [C_0402]  201.26 35.5 315 top
CU19  0.1U_0402_16V7K  [C_0402]  194.08 35.81 0 top
CU20  0.1U_0402_16V7K  [C_0402]  194.08 31.24 0 top
CU37  0.1U_0402_16V7K  [C_0402]  222.33 31.94 0 bottom
CU38  0.33U_0402_10V6K  [C_0402]  23.7 58.24 0 top
CU39  0.33U_0402_10V6K  [C_0402]  23.7 57.33 0 top
CU40  0.33U_0402_10V6K  [C_0402]  21.9 38.77 0 top
CU41  0.33U_0402_10V6K  [C_0402]  21.92 39.68 0 top
CV1  0.22U_0402_16V7K  [C_0402]  112.03 147.39 90 bottom
CV2  0.22U_0402_16V7K  [C_0402]  112.92 147.39 90 bottom
CV3  0.22U_0402_16V7K  [C_0402]  113.84 147.37 90 bottom
CV4  0.22U_0402_16V7K  [C_0402]  114.74 147.37 90 bottom
CV5  0.22U_0402_16V7K  [C_0402]  111.13 147.4 90 bottom
CV6  0.22U_0402_16V7K  [C_0402]  110.24 147.39 90.4 bottom
CV7  0.22U_0402_16V7K  [C_0402]  116.68 149.78 179.8 bottom
CV8  0.22U_0402_16V7K  [C_0402]  116.71 150.68 179.9 bottom
CV11  0.082U_0402_16V  [C_0402]  114.78 133.91 90 top
CV15  0.68U_0402_10V  [C_0402]  114.33 137.77 180 top
CV17  8.2P_0402_50V8D  [C_0402]  109.69 144.95 90 bottom
CV18  8.2P_0402_50V8D  [C_0402]  109.68 142.23 270 bottom
CV19  10U_0603_6.3V6M  [C_0603]  111.19 133.55 90 top
CV20  1U_0402_6.3V4Z  [C_0402]  117.75 132.74 270 top
CV21  0.1U_0402_10V6K  [C_0402]  116.85 132.57 270 top
CV25  0.1U_0402_10V7K  [C_0402]  46.9 89.48 270 top
CV26  1U_0402_6.3V4Z  [C_0402]  115.59 130.95 90 top
CV27  10U_0603_6.3V6M  [C_0603]  112.9 130.56 180 top
CV28  0.68U_0402_10V  [C_0402]  116.67 136.16 180 top
CV29  0.68U_0402_10V  [C_0402]  117.48 135.17 270 top
CV30  10U_0603_6.3V6M  [C_0603]  115.59 129.51 270 top
CV33  1U_0402_6.3V4Z  [C_0402]  117.57 130.23 270 top
CV34  0.1U_0402_10V6K  [C_0402]  116.67 130.23 270 top
CV35  0.1U_0402_10V6K  [C_0402]  113.89 130.86 90 top
CV38  10U_0603_6.3V6M  [C_0603]  111.67 124.58 90 top
CV39  0.1U_0402_10V6K  [C_0402]  110.2 131.62 0 top
CV40  2.2U_0402_6.3V6M  [C_0402]  127.58 137.94 180 top
CV41  2.2U_0402_6.3V6M  [C_0402]  128.25 136.97 180 top
CV42  2.2U_0402_6.3V6M  [C_0402]  128.25 136.07 180 top
CV43  10U_0603_6.3V6M  [C_0603]  149.01 149.09 90 top
CV44  10U_0603_6.3V6M  [C_0603]  150.28 149.09 90 top
CV45  10U_0603_6.3V6M  [C_0603]  151.55 149.09 90 top
CV46  1U_0402_6.3V4Z  [C_0402]  113.08 140.47 0 top
CV47  2.2U_0402_6.3V6M  [C_0402]  127.12 131.85 180 top
CV48  2.2U_0402_6.3V6M  [C_0402]  126.46 130.86 270 top
CV49  0.1U_0402_10V6K  [C_0402]  146.66 149 90 top
CV50  0.1U_0402_10V6K  [C_0402]  142.15 148.88 90 top
CV51  0.1U_0402_10V6K  [C_0402]  141.27 148.88 90 top
CV52  0.1U_0402_10V6K  [C_0402]  140.38 148.88 90 top
CV53  0.1U_0402_10V6K  [C_0402]  130.11 126.9 90 top
CV54  10U_0603_6.3V6M  [C_0603]  116.17 115.36 270 bottom
CV55  10U_0603_6.3V6M  [C_0603]  114.96 115.36 270 bottom
CV56  1U_0402_6.3V4Z  [C_0402]  124.48 143.08 124.1 top
CV57  1U_0402_6.3V4Z  [C_0402]  125.15 140.83 180 top
CV58  1U_0402_6.3V4Z  [C_0402]  123.93 139.04 90 top
CV59  1U_0402_6.3V4Z  [C_0402]  123.04 139.04 90 top
CV60  1U_0402_6.3V4Z  [C_0402]  122.15 139.04 90 top
CV61  10U_0603_6.3V6M  [C_0603]  110.87 137.44 59.3 top
CV62  1U_0402_6.3V4Z  [C_0402]  120.26 136.88 90 top
CV63  0.1U_0402_10V6K  [C_0402]  119.27 136.79 90 top
CV64  1U_0402_6.3V4Z  [C_0402]  119 134 90 top
CV65  1U_0402_6.3V4Z  [C_0402]  119.9 134.72 90 top
CV66  1U_0402_6.3V4Z  [C_0402]  108.68 136.07 90 bottom
CV67  10U_0603_6.3V6M  [C_0603]  121.83 129.66 90 top
CV68  10U_0603_6.3V6M  [C_0603]  118.97 130.3 270 top
CV69  10U_0603_6.3V6M  [C_0603]  120.62 130.3 270 top
CV70  10U_0603_6.3V6M  [C_0603]  118.97 131.38 0 top
CV71  1U_0402_6.3V4Z  [C_0402]  121.62 132.65 0 top
CV72  1U_0402_6.3V4Z  [C_0402]  125.08 130.81 180 top
CV73  1U_0402_6.3V4Z  [C_0402]  120.71 133.01 90 top
CV74  1U_0402_6.3V4Z  [C_0402]  121.03 135.67 270 top
CV75  1U_0402_6.3V4Z  [C_0402]  122.51 135.53 0 top
CV76  1U_0402_6.3V4Z  [C_0402]  119.99 123.18 135 top
CV77  1U_0402_6.3V4Z  [C_0402]  127.89 133.19 180 top
CV78  1U_0402_6.3V4Z  [C_0402]  125.2 131.94 90 top
CV79  1U_0402_6.3V4Z  [C_0402]  115.47 123.19 315 top
CV80  1U_0402_6.3V4Z  [C_0402]  121.26 120.59 270 top
CV81  10U_0603_6.3V6M  [C_0603]  128.34 124.84 270 top
CV82  1U_0402_6.3V4Z  [C_0402]  127.71 126.37 180 top
CV84  10U_0603_6.3V6M  [C_0603]  132.06 120.19 180 top
CV85  1U_0402_6.3V4Z  [C_0402]  130.93 123.16 180 top
CV86  0.1U_0402_10V6K  [C_0402]  131.5 121.27 180 top
CV87  1U_0402_6.3V4Z  [C_0402]  125.08 129.85 180 top
CV88  10U_0603_6.3V6M  [C_0603]  122.08 128.52 0 top
CV89  1U_0402_6.3V4Z  [C_0402]  117.89 120.57 90 top
CV90  1U_0402_6.3V4Z  [C_0402]  117 120.57 90 top
CV91  10U_0603_6.3V6M  [C_0603]  133.07 120.52 0 top
CV92  1U_0402_6.3V4Z  [C_0402]  133.06 121.57 0 top
CV93  0.1U_0402_10V6K  [C_0402]  131.67 124.03 0 top
CV94  1U_0402_6.3V4Z  [C_0402]  138.15 148.89 90 top
CV95  1U_0402_6.3V4Z  [C_0402]  138.15 146.44 270 top
CV96  120P_0402_50V8J  [C_0402]  150.94 115.73 90 bottom
CV97  68P_0402_50V8J  [C_0402]  147.64 116.58 270 bottom
CV98  0.1U_0402_16V4Z  [C_0402]  129.71 120.88 90 top
CV99  0.1U_0402_16V4Z  [C_0402]  127.09 122.33 0 top
CV100  1U_0402_6.3V4Z  [C_0402]  116.88 124.63 315 top
CV101  1U_0402_6.3V4Z  [C_0402]  123.79 126.22 0 top
CV102  1U_0402_6.3V4Z  [C_0402]  123.4 127.12 0 top
CV103  1U_0402_6.3V4Z  [C_0402]  120.53 127.01 270 top
CV104  1U_0402_6.3V4Z  [C_0402]  116.17 123.91 315 top
CV105  1U_0402_6.3V4Z  [C_0402]  123.79 125.33 0 top
CV106  1U_0402_6.3V4Z  [C_0402]  114.77 122.49 315 top
CV107  1U_0402_6.3V4Z  [C_0402]  121.97 127.45 270 top
CV108  1U_0402_6.3V4Z  [C_0402]  115.86 126.37 135 top
CV109  1U_0402_6.3V4Z  [C_0402]  115.19 125.72 135 top
CV110  1U_0402_6.3V4Z  [C_0402]  114.56 125.06 135 top
CV111  1U_0402_6.3V4Z  [C_0402]  123.4 132.66 0 top
CV112  1U_0402_6.3V4Z  [C_0402]  122.49 133.61 180 top
CV113  1U_0402_6.3V4Z  [C_0402]  123.4 133.73 90 top
CV114  1U_0402_6.3V4Z  [C_0402]  126.1 133.73 270 top
CV115  1U_0402_6.3V4Z  [C_0402]  127.36 135.17 0 top
CV116  1U_0402_6.3V4Z  [C_0402]  126.1 134.81 90 top
CV117  1U_0402_6.3V4Z  [C_0402]  125.19 134.89 180 top
CV118  1U_0402_6.3V4Z  [C_0402]  125.16 135.78 180 top
CV119  1U_0402_6.3V4Z  [C_0402]  126.76 128.18 90 top
CV120  1U_0402_6.3V4Z  [C_0402]  125.15 141.72 180 top
CV121  1U_0402_6.3V4Z  [C_0402]  124.82 139.04 90 top
CV122  10U_0603_6.3V6M  [C_0603]  122.76 143.07 90 top
CV123  10U_0402_6.3V6M  [C_0402]  109.84 136.16 90 bottom
CV124  0.1U_0402_10V6K  [C_0402]  127.27 125.38 180 top
CV125  0.1U_0402_10V6K  [C_0402]  120.29 120.59 270 top
CV126  0.1U_0402_10V6K  [C_0402]  113.9 124.41 135 top
CV127  0.1U_0402_10V6K  [C_0402]  121.46 136.93 90 top
CV153  0.1U_0402_10V6K  [C_0402]  164.24 121.85 0 bottom
CV155  0.1U_0402_10V6K  [C_0402]  163.98 140.33 0 bottom
CV157  0.1U_0402_10V6K  [C_0402]  163.98 137.22 0 bottom
CV158  0.1U_0402_10V6K  [C_0402]  163.98 136.2 0 bottom
CV160  0.1U_0402_10V6K  [C_0402]  164.24 125.78 0 bottom
CV161  0.1U_0402_10V6K  [C_0402]  164.24 126.86 0 bottom
CV162  0.1U_0402_10V6K  [C_0402]  164.24 127.94 0 bottom
CV164  0.1U_0402_10V6K  [C_0402]  160.7 116.65 270 bottom
CV165  0.1U_0402_10V6K  [C_0402]  159.62 116.65 270 bottom
CV166  0.1U_0402_10V6K  [C_0402]  158.54 116.65 270 bottom
CV169  1U_0402_6.3V4Z  [C_0402]  161.61 116.64 270 top
CV170  1U_0402_6.3V4Z  [C_0402]  164.24 124.7 0 bottom
CV173  1U_0402_6.3V4Z  [C_0402]  164.24 130.1 0 bottom
CV174  0.01U_0402_16V7K  [C_0402]  128.61 127.09 90 top
CV175  0.01U_0402_16V7K  [C_0402]  128.61 129.06 180 top
CV176  0.01U_0402_16V7K  [C_0402]  128.43 130.32 90 top
CV177  0.01U_0402_16V7K  [C_0402]  127.36 130.86 270 top
CV178  0.01U_0402_16V7K  [C_0402]  147.55 149 90 top
CV179  0.01U_0402_16V7K  [C_0402]  110.2 132.51 0 top
CV180  1U_0402_6.3V4Z  [C_0402]  123.05 136.53 90 top
CV181  1U_0402_6.3V4Z  [C_0402]  126.04 137.06 180 top
CV198  0.1U_0402_10V6K  [C_0402]  157.43 149.06 90 top
CV210  0.1U_0402_10V6K  [C_0402]  160.3 149.08 90 top
CV211  0.1U_0402_10V6K  [C_0402]  159.34 149.06 90 top
CV213  0.1U_0402_10V6K  [C_0402]  158.38 149.06 90 top
CV216  0.1U_0402_10V6K  [C_0402]  164.24 120.77 0 bottom
CV219  0.1U_0402_10V6K  [C_0402]  157.61 116.64 270 bottom
CV221  0.1U_0402_10V6K  [C_0402]  151.93 116.65 270 bottom
CV225  10U_0603_6.3V6M  [C_0603]  163.77 119.87 0 top
CV227  1U_0402_6.3V4Z  [C_0402]  164.24 129.02 0 top
CV230  0.1U_0402_10V6K  [C_0402]  160.31 149.02 90 bottom
CV233  0.1U_0402_10V6K  [C_0402]  159.3 149.02 90 bottom
CV235  0.1U_0402_10V6K  [C_0402]  158.28 149.02 90 bottom
CV238  10U_0603_6.3V6M  [C_0603]  152.8 149.09 90 top
CV242  1U_0402_6.3V4Z  [C_0402]  163.98 136.2 0 top
CV243  1U_0402_6.3V4Z  [C_0402]  161.28 149.08 90 top
CV247  1U_0402_6.3V4Z  [C_0402]  162.24 149.08 90 top
CV248  1U_0402_6.3V4Z  [C_0402]  163.18 149.08 90 top
CV304  0.22U_0402_16V7K  [C_0402]  143.59 88.2 0 bottom
CV305  0.22U_0402_16V7K  [C_0402]  143.59 83.75 0 bottom
CV306  0.22U_0402_16V7K  [C_0402]  143.59 81.97 0 bottom
CV307  0.22U_0402_16V7K  [C_0402]  143.59 86.42 0 bottom
CV308  0.22U_0402_16V7K  [C_0402]  143.59 84.64 0 bottom
CV309  0.22U_0402_16V7K  [C_0402]  143.59 85.53 0 bottom
CV312  0.22U_0402_16V7K  [C_0402]  143.59 82.86 0 bottom
CV313  0.22U_0402_16V7K  [C_0402]  143.59 87.31 0 bottom
CV333  1U_0402_6.3V4Z  [C_0402]  160.63 116.65 270 top
CV334  1U_0402_6.3V4Z  [C_0402]  159.62 116.65 270 top
CV335  1U_0402_6.3V4Z  [C_0402]  158.54 116.65 270 top
CV336  1U_0402_6.3V4Z  [C_0402]  157.46 116.65 270 top
CV341  1U_0402_6.3V4Z  [C_0402]  163.98 137.21 0 top
CV342  1U_0402_6.3V4Z  [C_0402]  163.98 140.32 0 top
CV343  1U_0402_6.3V4Z  [C_0402]  164.05 147.25 0 top
CV344  1U_0402_6.3V4Z  [C_0402]  164.05 148.26 0 top
CV390  1U_0402_6.3V6K  [C_0402]  165.13 121.86 270 top
CV391  1U_0402_6.3V6K  [C_0402]  154.6 116.65 270 bottom
CV394  1U_0402_6.3V6K  [C_0402]  163.98 144.39 0 top
CV395  1U_0402_6.3V6K  [C_0402]  154.64 149.09 0 bottom
CW5  10P_0402_50V8J  [C_0402]  216.15 31.69 270 top
CW6  10P_0402_50V8J  [C_0402]  223.24 48.18 90 top
CW7  10P_0402_50V8J  [C_0402]  71.89 136.47 270 top
CW8  10U_0603_6.3V6M  [C_0603]  73.67 116.26 90 top
CW9  0.1U_0402_10V7K~D  [C_0402]  75.85 118.18 270 top
CW10  10P_0402_50V8J  [C_0402]  70.96 136.47 270 top
CW11  10P_0402_50V8J  [C_0402]  74.9 118.18 270 top
CW12  10U_0603_6.3V6M  [C_0603]  71.03 117.47 0 top
CW13  0.1U_0402_10V7K~D  [C_0402]  76.81 118.18 270 top
CW14  10P_0402_50V8J  [C_0402]  72.25 118.55 180 top
CW15  2.2U_0402_6.3V6M  [C_0402]  72.81 136.47 270 top
CW16  2.2U_0402_6.3V6M  [C_0402]  72.86 137.41 0 top
CX2  0.1U_0402_10V7K  [C_0402]  99.03 31.69 270 bottom
CX3  0.1U_0402_10V7K  [C_0402]  215.26 31.69 270 top
CX8  10U_0402_6.3V6M  [C_0402]  99.92 31.69 270 bottom
CX9  10U_0402_6.3V6M  [C_0402]  100.22 36.83 0 top
CX10  0.1U_0402_10V7K  [C_0402]  100.29 38.29 0 top
CX11  0.1U_0402_10V7K  [C_0402]  100.29 39.24 0 top
CX12  0.1U_0402_10V7K  [C_0402]  103.35 39.19 270 top
CX13  10U_0402_6.3V6M  [C_0402]  100.81 31.69 270 bottom
D1  -  [RB751V-40_SOD323-2]  33.18 68.31 270 top
D2  -  [L30ESD24VC3-2_SOT23-3]  13.81 131.47 180 top
D5  -  [RB751V-40_SOD323-2]  115.38 110.93 270 bottom
D6  -  [RB751V-40_SOD323-2]  118.64 109.02 0 bottom
DA1  -  [L03ESDL5V0CC3-2_SOT23-3]  27.34 4.59 180 top
DA2  -  [L03ESDL5V0CC3-2_SOT23-3]  20.29 4.42 90 top
DA3  BAT54C SOT23-3  [BAT54C-7-F_SOT23-3]  33.03 21.08 270 top
DA5  AZ5123-02S.R7G_SOT23-3  [AZ5123-02SPR7G_SOT23-3]  17.31 7.84 0 top
DA6  -  [L03ESDL5V0CC3-2_SOT23-3]  17.31 22.12 180 top
DC1  -  [BAS40C_SOT23-3]  158.12 28.51 270 top
DF1  -  [DB2J31400L_SOD323-2]  179.52 71.05 180 top
DH1  -  [DB2J31400L_SOD323-2]  222.47 56.35 270 top
DH2  -  [DB2J31400L_SOD323-2]  224.13 56.35 270 top
DT1  S SCH DIO RB551V-30 SOD323 PANJIT  [RB551V-30_SOD323-2]  31.03 121.28 180 top
DT2  S SCH DIO RB551V-30 SOD323 PANJIT  [RB551V-30_SOD323-2]  31.03 119.63 180 top
DT3  AZ5B75-01B.R7G_CSP0603P2Y2  [ESD101-B1-02ELS_TSSLP-2-4-2]  9.94 123.75 90 top
DT4  AZ5B75-01B.R7G_CSP0603P2Y2  [ESD101-B1-02ELS_TSSLP-2-4-2]  9.94 123 270 top
DT5  AZ5B75-01B.R7G_CSP0603P2Y2  [ESD101-B1-02ELS_TSSLP-2-4-2]  10.4 119.92 90 top
DT6  AZ5B75-01B.R7G_CSP0603P2Y2  [ESD101-B1-02ELS_TSSLP-2-4-2]  10.4 119.3 270 top
DT7  AZ5B75-01B.R7G_CSP0603P2Y2  [ESD101-B1-02ELS_TSSLP-2-4-2]  12.15 126.05 90 top
DT8  AZ5B75-01B.R7G_CSP0603P2Y2  [ESD101-B1-02ELS_TSSLP-2-4-2]  12.15 125.43 270 top
DT9  AZ5B75-01B.R7G_CSP0603P2Y2  [ESD101-B1-02ELS_TSSLP-2-4-2]  11.21 118.02 90 top
DT10  AZ5B75-01B.R7G_CSP0603P2Y2  [ESD101-B1-02ELS_TSSLP-2-4-2]  11.21 117.4 270 top
DU2  -  [AZC199-02SPR7G_SOT23-3]  219.49 35.83 0 bottom
DX1  -  [RB751V-40_SOD323-2]  212.38 45.9 270 top
DX3  -  [AZC199-02SPR7G_SOT23-3]  210.05 40.19 270 bottom
EC1  .1U_0402_16V7K  [C_0402]  31.92 74.61 180 top
EC2  1000P_0402_50V7K  [C_0402]  30.58 64.18 90 top
ED2  -  [L03ESDL5V0CC3-2_SOT23-3]  38.45 60.61 0 top
EU2  -  [AZC199-02SPR7G_SOT23-3]  27.06 57.34 270 top
EU3  -  [L05ESDL5V0NA-4_SLP2510P8-10-9]  20.03 57.61 270 top
EU4  -  [AZC199-02SPR7G_SOT23-3]  29.33 39.49 270 bottom
EU5  -  [L05ESDL5V0NA-4_SLP2510P8-10-9]  20.72 34.72 0 top
EU7  -  [L05ESDL5V0NA-4_SLP2510P8-10-9]  25.55 131.42 90 bottom
EU8  -  [L05ESDL5V0NA-4_SLP2510P8-10-9]  10.65 120.28 270 bottom
EU4012  -  [TVNST52302AB0_SOT523-3]  218.66 25.67 180 top
F1  SMD1812P150TF/24 1.5A UL/CSA/TUV  [F_SMD1812P110TF-24]  207.26 52.63 90 top
F2  1.1A_24V_SMD1812P110TF-24  [F_SMD1812P110TF-24]  212.39 37.78 180 top
F3  0.5A_13.2V_MF-NSMF050-2  [F_MF-NSMF050-2]  91.69 34.35 0 top
FD1  FIDUCAL  [FIDUCIAL_C40M80]  13.88 114.74 0 top
FD2  FIDUCAL  [FIDUCIAL_C40M80]  223.33 26.42 0 top
FD3  FIDUCAL  [FIDUCIAL_C40M80]  20.94 3.03 180 bottom
FD4  FIDUCAL  [FIDUCIAL_C40M80]  141.64 149.21 180 bottom
FI1  1.5A_6V_1206L150PR~D  [F_1206L150PR]  16.1 101.08 90 top
H1  HOLEA  [H_3P0]  6.85 130.5 0 top
H3  HOLEA  [H_5P0-G]  169.05 109.5 0 top
H4  HOLEA  [H_3P0-G]  7.9 85.8 0 top
H5  HOLEA  [H_3P0-G]  8 41.2 0 top
H6  HOLEA  [H_3P0-G]  207.45 63.85 0 top
H7  HOLEA  [H_3P0-G]  141.55 27.1 0 top
H8  HOLEA  [H_3P3]  6.9 112.6 0 top
H9  HOLEA  [H_3P5]  142.95 117.18 180 bottom
H10  HOLEA  [H_3P5]  101.31 130.35 180 bottom
H11  HOLEA  [H_3P2]  126.01 153.05 180 bottom
H12  HOLEA  [H_3P2]  45.5 129.9 0 top
H13  HOLEA  [H_3P0X4P0]  213.85 65.5 270 top
H14  HOLEA  [H_5P6N]  19.1 111.3 90 top
HCPU1  HOLEA  [H_4P0X3P7]  113.08 100.78 0 top
HCPU2  HOLEA  [H_3P7]  137.38 100.78 0 top
HCPU3  HOLEA  [H_4P0]  113.08 39.78 0 top
HCPU4  HOLEA  [H_3P7X4P0]  137.38 39.78 0 top
J1  -  [JUMP_43X118]  46.33 102.65 270 top
